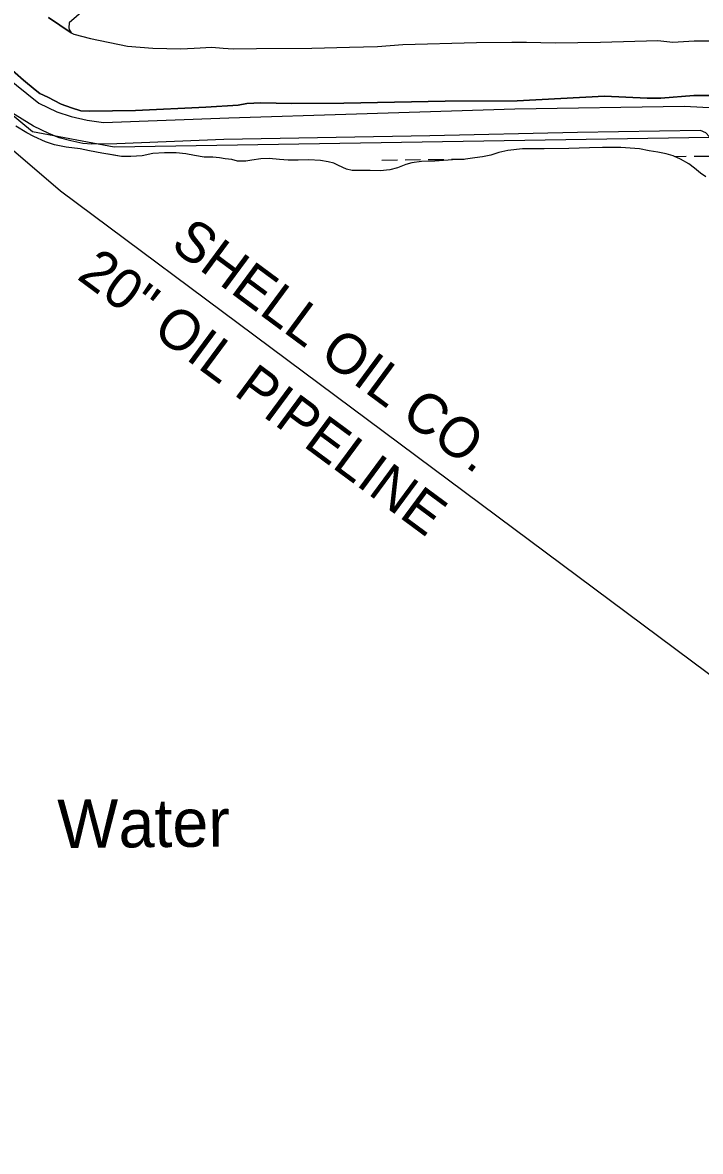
# Model space of a CAD drawing. Extents: x 3702978 to 3741108, y 397120 to 422907.
# Drawn here: x 3708229 to 3709632, y 415410 to 417744 of the extents above; entities that cross this region are included whole.
import ezdxf

# ---------------------------------------------------------------- set-up
doc = ezdxf.new("R2010")
doc.units = 0
for name, color, linetype in [('V-LEVE-TOET', 7, 'Continuous'), ('V-RIVR-IDEN', 7, 'Continuous'), ('V-TOPO-SHOR', 7, 'Continuous'), ('V-UTIL-IDEN', 7, 'Continuous'), ('V-UTIL-LINE', 7, 'Continuous'), ('V-WETL-SWMP', 7, 'Continuous')]:
    doc.layers.add(name, color=color, linetype=linetype)

msp = doc.modelspace()

# ---------------------------------------------------------------- linework, layer by layer
at = {"layer": 'V-LEVE-TOET'}
for p, q in [((3708191.645, 417634.499), (3708263.042, 417577.532)), ((3708263.042, 417577.532), (3708300.007, 417559.838)), ((3709247.776, 417565.969), (3709599.012, 417571.267)), ((3709599.012, 417571.267), (3709661.925, 417568.14)), ((3708251.717, 417529.832), (3708204.783, 417559.131)), ((3708300.007, 417559.838), (3708329.727, 417550.175)), ((3708329.727, 417550.175), (3708363.026, 417542.337)), ((3708396.306, 417537.193), (3708655.869, 417547.203)), ((3708655.869, 417547.203), (3708919.938, 417555.451)), ((3708919.938, 417555.451), (3709247.776, 417565.969)), ((3708283.273, 417514.794), (3708251.717, 417529.832)), ((3708363.026, 417542.337), (3708396.306, 417537.193)), ((3709631.727, 417521.2), (3709377.513, 417516.621)), ((3708304.897, 417505.967), (3708283.273, 417514.794)), ((3708329.201, 417499.862), (3708304.897, 417505.967)), ((3708353.505, 417493.753), (3708329.201, 417499.862)), ((3708645.423, 417502.207), (3708424.48, 417493.382)), ((3709072.107, 417509.862), (3708645.423, 417502.207)), ((3709377.513, 417516.621), (3709072.107, 417509.862)), ((3708372.377, 417492.995), (3708353.505, 417493.753)), ((3708424.48, 417493.382), (3708372.377, 417492.995))]:
    msp.add_line(p, q, dxfattribs=at)
for points in [[(3707018.762, 418605.931), (3707101.491, 418535.599), (3707321.175, 418350.359), (3707577.788, 418152.818), (3707836.327, 417937.321), (3708018.941, 417784.151), (3708103.913, 417713.806), (3708191.645, 417634.499), (3708263.042, 417577.532), (3708300.009, 417559.838), (3708329.727, 417550.175), (3708363.026, 417542.337), (3708396.306, 417537.193), (3708655.869, 417547.203), (3708919.938, 417555.451), (3709247.776, 417565.967), (3709599.012, 417571.267), (3709661.925, 417568.14), (3709679.007, 417566.471), (3709695.211, 417562.099), (3709702.465, 417553.169), (3709837.385, 417289.141), (3710019.62, 416944.608), (3710051.51, 416884.651)], [(3709976.768, 416908.354), (3709846.458, 417156.244), (3709698.858, 417433.654), (3709657.954, 417498.037), (3709649.786, 417508.756), (3709642.547, 417515.89), (3709631.727, 417521.2), (3709377.513, 417516.621), (3709072.107, 417509.862), (3708645.423, 417502.207), (3708424.48, 417493.382), (3708372.377, 417492.995), (3708353.505, 417493.753), (3708329.201, 417499.862), (3708304.9, 417505.969), (3708283.273, 417514.794), (3708251.717, 417529.832), (3708204.783, 417559.131)]]:
    msp.add_lwpolyline(points, dxfattribs=at)
at = {"layer": 'V-TOPO-SHOR'}
for p, q in [((3708282.83, 417754.674), (3708329.502, 417723.139)), ((3708329.502, 417723.139), (3708334.915, 417720.483)), ((3708334.915, 417720.483), (3708369.905, 417711.549)), ((3708369.905, 417711.549), (3708446.306, 417695.575)), ((3709425.047, 417703.753), (3709543.579, 417707.388)), ((3709543.579, 417707.388), (3709574.852, 417703.943)), ((3709618.952, 417706.11), (3709659.387, 417706.409)), ((3708446.306, 417695.575), (3708498.722, 417691.366)), ((3708498.722, 417691.366), (3708556.636, 417689.959)), ((3708556.636, 417689.959), (3708584.2, 417691.082)), ((3708584.2, 417691.082), (3708620.945, 417693.193)), ((3708620.945, 417693.193), (3708643.934, 417691.526)), ((3708643.934, 417691.526), (3708665.085, 417689.845)), ((3708665.085, 417689.845), (3708712.875, 417690.199)), ((3708712.875, 417690.199), (3708827.75, 417691.051)), ((3708827.75, 417691.051), (3708905.852, 417693.468)), ((3708905.852, 417693.468), (3708963.743, 417694.815)), ((3708963.743, 417694.815), (3709016.1, 417698.88)), ((3709016.1, 417698.88), (3709168.635, 417702.77)), ((3709168.635, 417702.77), (3709241.239, 417703.308)), ((3709241.239, 417703.308), (3709271.566, 417703.533)), ((3709271.566, 417703.533), (3709331.314, 417702.139)), ((3709331.314, 417702.139), (3709425.047, 417703.753)), ((3709574.852, 417703.943), (3709618.952, 417706.11)), ((3708230.848, 417625.048), (3708196.622, 417655.123)), ((3708254.893, 417605.006), (3708230.848, 417625.048)), ((3708265.056, 417597.73), (3708254.893, 417605.006)), ((3708281.661, 417589.581), (3708265.056, 417597.73)), ((3709433.229, 417591.686), (3709252.245, 417582.075)), ((3709521.487, 417587.748), (3709433.229, 417591.686)), ((3709617.95, 417593.056), (3709549.977, 417587.959)), ((3709657.466, 417593.349), (3709617.95, 417593.056)), ((3708309.34, 417575.081), (3708281.661, 417589.581)), ((3708330.53, 417567.884), (3708309.34, 417575.081)), ((3708349.878, 417561.595), (3708330.53, 417567.884)), ((3708608.079, 417569.025), (3708462.915, 417562.434)), ((3708675.139, 417573.199), (3708608.079, 417569.025)), ((3708693.493, 417577.01), (3708675.139, 417573.199)), ((3708721.975, 417578.141), (3708693.493, 417577.01)), ((3708785.401, 417576.772), (3708721.975, 417578.141)), ((3708893.845, 417577.577), (3708785.401, 417576.772)), ((3709103.357, 417581.888), (3708893.845, 417577.577)), ((3709252.245, 417582.075), (3709103.357, 417581.888)), ((3709549.977, 417587.959), (3709521.487, 417587.748)), ((3708367.345, 417560.806), (3708349.878, 417561.595)), ((3708462.915, 417562.434), (3708367.345, 417560.806))]:
    msp.add_line(p, q, dxfattribs=at)
for points in [[(3710109.941, 419343.07), (3710102.192, 419317.894), (3710024.56, 419252.991), (3709904.068, 419143.658), (3709807.267, 419061.151), (3709657.56, 418925.872), (3709391.894, 418689.564), (3709087.868, 418420.809), (3708775.651, 418141.883), (3708483.518, 417880.567), (3708325.554, 417743.388), (3708324.71, 417733.272), (3708325.435, 417729.635), (3708329.5, 417723.139), (3708282.83, 417754.672)], [(3708282.83, 417754.672), (3708329.5, 417723.139), (3708334.915, 417720.483), (3708369.905, 417711.549), (3708446.306, 417695.575), (3708498.722, 417691.366), (3708556.636, 417689.959), (3708584.198, 417691.082), (3708620.945, 417693.193), (3708643.934, 417691.526), (3708665.085, 417689.845), (3708712.873, 417690.199), (3708827.75, 417691.051), (3708905.852, 417693.468), (3708963.743, 417694.815), (3709016.1, 417698.88), (3709168.635, 417702.77), (3709241.239, 417703.308), (3709271.566, 417703.533), (3709331.314, 417702.139), (3709425.047, 417703.753), (3709543.579, 417707.388), (3709574.852, 417703.943), (3709618.952, 417706.11), (3709659.387, 417706.409)], [(3708196.62, 417655.123), (3708230.848, 417625.048), (3708254.893, 417605.006), (3708265.056, 417597.73), (3708281.661, 417589.581), (3708309.34, 417575.081), (3708330.53, 417567.884), (3708349.878, 417561.595), (3708367.345, 417560.806), (3708462.915, 417562.434), (3708608.079, 417569.025), (3708675.139, 417573.199), (3708693.493, 417577.01), (3708721.975, 417578.141), (3708785.401, 417576.772), (3708893.845, 417577.577), (3709103.357, 417581.888), (3709252.245, 417582.075), (3709433.229, 417591.686), (3709521.487, 417587.748), (3709549.977, 417587.959), (3709617.95, 417593.056), (3709657.466, 417593.349)], [(3708276.604, 417497.283), (3708252.741, 417508.801), (3708237.873, 417516.486), (3708215.162, 417529.961)], [(3709643.007, 417425.169), (3709631.647, 417432.88), (3709619.097, 417443.313), (3709607.727, 417452.193), (3709590.507, 417461.421), (3709575.251, 417468.325), (3709560.799, 417472.505), (3709543.231, 417476.273), (3709525.276, 417479.259), (3709505.365, 417483.398), (3709467.148, 417485.843), (3709429.335, 417485.954), (3709402.443, 417485.362), (3709359.576, 417483.875), (3709308.129, 417483.105), (3709263.693, 417482.775), (3709232.922, 417479.429), (3709214.631, 417475.394), (3709197.911, 417469.814), (3709180.788, 417466.178), (3709164.822, 417464.112), (3709145.737, 417462.021), (3709118.85, 417460.653), (3709082.23, 417457.651), (3709054.56, 417457.057), (3709034.311, 417454.177), (3709022.255, 417450.581), (3709005.154, 417443.827), (3708988.815, 417439.417), (3708968.949, 417437.32), (3708948.285, 417437.947), (3708929.572, 417438.199), (3708911.251, 417438.453), (3708899.149, 417440.701), (3708882.718, 417448.764), (3708872.939, 417453.37), (3708861.222, 417456.401), (3708845.615, 417458.625), (3708821.434, 417460.395), (3708799.217, 417459.84), (3708778.948, 417459.69), (3708760.62, 417460.723), (3708739.557, 417462.906), (3708722.018, 417462.386), (3708703.717, 417459.912), (3708691.261, 417457.481), (3708674.107, 417457.743), (3708662.001, 417460.772), (3708648.347, 417462.23), (3708636.637, 417464.481), (3708622.591, 417465.937), (3708604.661, 417465.804), (3708585.144, 417469.558), (3708566.8, 417472.929), (3708546.901, 417475.12), (3708522.735, 417474.942), (3708498.581, 417473.203), (3708476.395, 417468.751), (3708453.406, 417467.409), (3708433.917, 417467.266), (3708414.404, 417470.629), (3708392.937, 417474.368), (3708367.955, 417478.862), (3708348.045, 417483.001), (3708319.172, 417486.685), (3708294.971, 417491.182), (3708276.604, 417497.283)]]:
    msp.add_lwpolyline(points, dxfattribs=at)
at = {"layer": 'V-UTIL-LINE'}
msp.add_lwpolyline([(3707020.005, 418499.715), (3708307.429, 417396.327), (3712056.489, 414605.301), (3716586.141, 411403.533), (3719513.767, 409439.311), (3724244.445, 405645.856), (3728699.465, 402788.238)], dxfattribs=at)
at = {"layer": 'V-WETL-SWMP'}
for p, q in [((3707019.612, 418533.278), (3708249.756, 417518.841)), ((3708237.872, 417516.486), (3708215.163, 417529.961)), ((3708252.741, 417508.801), (3708237.872, 417516.486)), ((3708249.756, 417518.841), (3708418.598, 417487.172)), ((3708276.605, 417497.283), (3708252.741, 417508.801)), ((3708294.971, 417491.183), (3708276.605, 417497.283)), ((3708418.598, 417487.172), (3709650.367, 417506.952)), ((3708319.172, 417486.685), (3708294.971, 417491.183)), ((3708348.045, 417483.001), (3708319.172, 417486.685)), ((3708367.955, 417478.861), (3708348.045, 417483.001)), ((3708392.936, 417474.368), (3708367.955, 417478.861)), ((3708433.918, 417467.266), (3708392.936, 417474.368)), ((3708498.581, 417473.203), (3708476.395, 417468.75)), ((3708522.736, 417474.941), (3708498.581, 417473.203)), ((3708546.902, 417475.12), (3708522.736, 417474.941)), ((3708566.799, 417472.929), (3708546.902, 417475.12)), ((3708585.144, 417469.557), (3708566.799, 417472.929)), ((3709214.632, 417475.395), (3709197.912, 417469.814)), ((3709232.923, 417479.428), (3709214.632, 417475.395)), ((3709263.693, 417482.775), (3709232.923, 417479.428)), ((3709308.128, 417483.105), (3709263.693, 417482.775)), ((3709359.576, 417483.876), (3709308.128, 417483.105)), ((3709402.443, 417485.363), (3709359.576, 417483.876)), ((3709429.335, 417485.953), (3709402.443, 417485.363)), ((3709467.147, 417485.843), (3709429.335, 417485.953)), ((3709505.366, 417483.398), (3709467.147, 417485.843)), ((3709525.276, 417479.258), (3709505.366, 417483.398)), ((3709543.23, 417476.273), (3709525.276, 417479.258)), ((3709560.799, 417472.505), (3709543.23, 417476.273)), ((3708453.407, 417467.41), (3708433.918, 417467.266)), ((3708476.395, 417468.75), (3708453.407, 417467.41)), ((3708604.662, 417465.804), (3708585.144, 417469.557)), ((3708622.592, 417465.937), (3708604.662, 417465.804)), ((3708636.636, 417464.481), (3708622.592, 417465.937)), ((3708648.347, 417462.23), (3708636.636, 417464.481)), ((3708662.001, 417460.772), (3708648.347, 417462.23)), ((3708674.107, 417457.743), (3708662.001, 417460.772)), ((3708691.26, 417457.48), (3708674.107, 417457.743)), ((3708703.716, 417459.912), (3708691.26, 417457.48)), ((3708722.018, 417462.386), (3708703.716, 417459.912)), ((3708739.556, 417462.906), (3708722.018, 417462.386)), ((3708760.621, 417460.723), (3708739.556, 417462.906)), ((3708778.949, 417459.69), (3708760.621, 417460.723)), ((3708799.218, 417459.84), (3708778.949, 417459.69)), ((3708821.433, 417460.395), (3708799.218, 417459.84)), ((3708845.614, 417458.625), (3708821.433, 417460.395)), ((3708861.222, 417456.402), (3708845.614, 417458.625)), ((3708872.939, 417453.371), (3708861.222, 417456.402)), ((3708882.718, 417448.765), (3708872.939, 417453.371)), ((3708972.553, 417459.75), (3709004.551, 417460.148)), ((3709022.254, 417450.58), (3709005.153, 417443.826)), ((3709020.549, 417460.346), (3709052.547, 417460.744)), ((3709034.311, 417454.178), (3709022.254, 417450.58)), ((3709054.56, 417457.056), (3709034.311, 417454.178)), ((3709082.231, 417457.651), (3709054.56, 417457.056)), ((3709068.546, 417460.943), (3709100.543, 417461.34)), ((3709118.85, 417460.652), (3709082.231, 417457.651)), ((3709116.542, 417461.539), (3709142.659, 417461.863)), ((3709145.737, 417462.02), (3709118.85, 417460.652)), ((3709164.821, 417464.111), (3709145.737, 417462.02)), ((3709180.788, 417466.178), (3709164.821, 417464.111)), ((3709197.912, 417469.814), (3709180.788, 417466.178)), ((3709575.252, 417468.324), (3709560.799, 417472.505)), ((3709590.506, 417461.421), (3709575.252, 417468.324)), ((3709577.59, 417467.266), (3709602.412, 417467.574)), ((3709607.726, 417452.193), (3709590.506, 417461.421)), ((3709619.096, 417443.312), (3709607.726, 417452.193)), ((3709618.411, 417467.773), (3709650.409, 417468.171)), ((3708899.15, 417440.701), (3708882.718, 417448.765)), ((3708911.25, 417438.452), (3708899.15, 417440.701)), ((3708948.285, 417437.947), (3708911.25, 417438.452)), ((3708968.949, 417437.321), (3708948.285, 417437.947)), ((3708988.814, 417439.417), (3708968.949, 417437.321)), ((3709005.153, 417443.826), (3708988.814, 417439.417)), ((3709631.647, 417432.881), (3709619.096, 417443.312))]:
    msp.add_line(p, q, dxfattribs=at)

# ---------------------------------------------------------------- texts
at = {"layer": 'V-RIVR-IDEN'}
msp.add_text('Water', height=99.9998, rotation=0.572928, dxfattribs=at).set_placement((3708301.824, 416036.96))
at = {"layer": 'V-UTIL-IDEN'}
for s, p in [('SHELL OIL CO.', (3708532.585, 417278.606)), ('20" OIL PIPELINE', (3708339.26, 417215.737))]:
    msp.add_text(s, height=83, rotation=323.520783, dxfattribs=at).set_placement(p)

doc.saveas('drawing.dxf')
